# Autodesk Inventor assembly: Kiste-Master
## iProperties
Manager: Dr.-Ing. Roland Schröder
Company: www.Das-Entwicklungsbuero.de
Created: 2006-09
Part Number: Kiste-Master
Project: 12107
Document SubType Name: Assembly
Designer: rsc
Engineer: Dr.-Ing. Roland Schröder
Oberflächen: Ra 3,2
Toleranzen: ISO 2768 - m
a: 17.000 oE
b: 10.000 mm
d: 34.000 mm
Author: rsc
